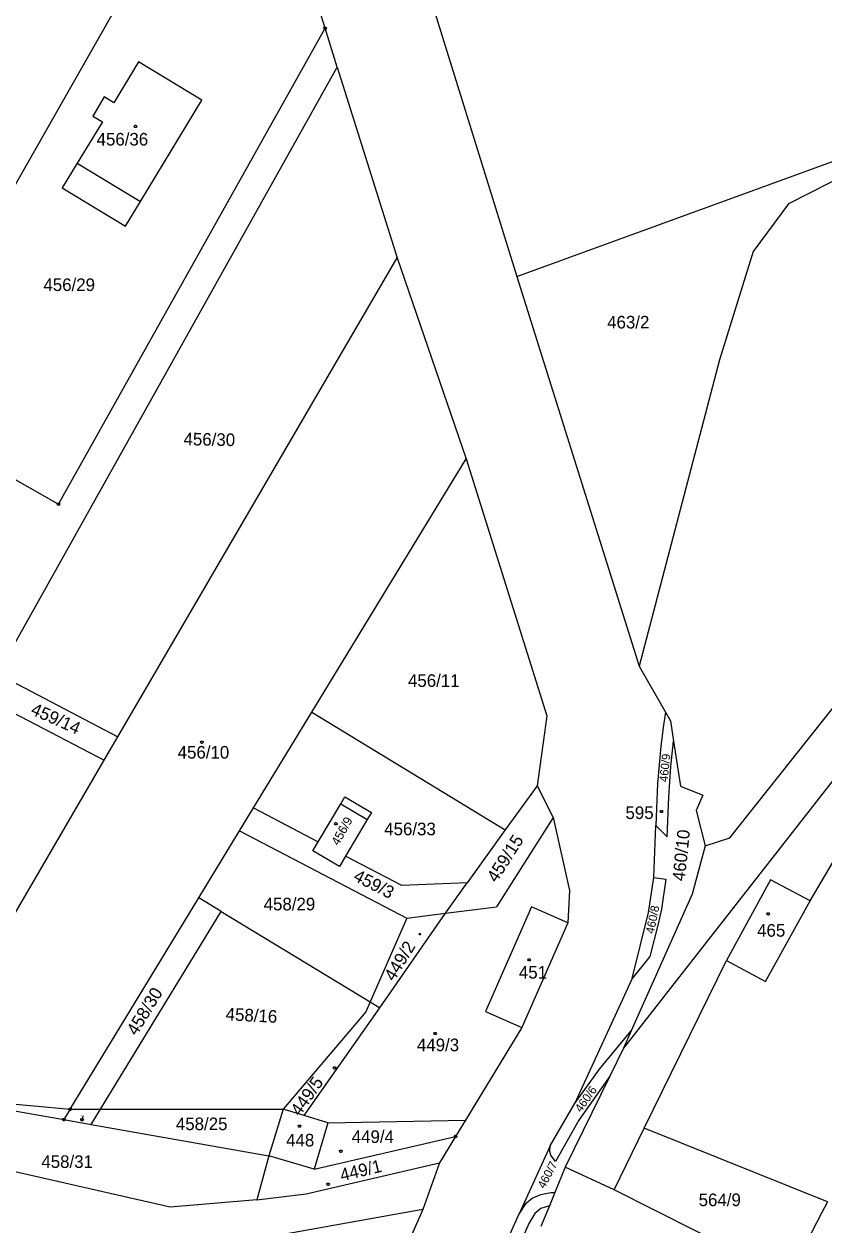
# Model space of a CAD drawing. Extents: x -634640 to -629202, y -1196156 to -1190068.
# Drawn here: x -631593.2 to -631485.4, y -1192430.1 to -1192268.2 of the extents above; entities that cross this region are included whole.
import ezdxf

# ---------------------------------------------------------------- set-up
doc = ezdxf.new("R2010")
doc.units = 0
for name, color, linetype in [('Vrstva 1', 7, 'Continuous'), ('Vrstva 2', 7, 'Continuous'), ('Vrstva 3', 7, 'Continuous'), ('Vrstva 4', 7, 'Continuous'), ('Vrstva 5', 7, 'Continuous'), ('Vrstva 7', 7, 'Continuous'), ('Vrstva 8', 7, 'Continuous')]:
    doc.layers.add(name, color=color, linetype=linetype)

msp = doc.modelspace()

# ---------------------------------------------------------------- linework, layer by layer
at = {"layer": 'Vrstva 1'}
for p, q in [((-631562.06, -1192188.79), (-631526.81, -1192302.22)), ((-631611.53, -1192319.92), (-631563.25, -1192234.99)), ((-631552.68, -1192268.74), (-631557.54, -1192253.21)), ((-631551.04, -1192273.99), (-631552.68, -1192268.74)), ((-631596.84, -1192355.81), (-631551.04, -1192273.99)), ((-631577.8, -1192273.3), (-631581.15, -1192278.82)), ((-631569.29, -1192278.43), (-631577.8, -1192273.3)), ((-631551.04, -1192273.99), (-631542.97, -1192299.72)), ((-631582.43, -1192278.02), (-631583.98, -1192280.59)), ((-631581.15, -1192278.82), (-631582.43, -1192278.02)), ((-631577.54, -1192292.12), (-631569.29, -1192278.43)), ((-631583.98, -1192280.59), (-631582.69, -1192281.35)), ((-631526.81, -1192302.22), (-631465.53, -1192279.88)), ((-631465.53, -1192279.88), (-631490.22, -1192292.44)), ((-631582.69, -1192281.35), (-631586.08, -1192286.94)), ((-631586.08, -1192286.94), (-631588.1, -1192290.27)), ((-631588.1, -1192290.27), (-631579.56, -1192295.46)), ((-631579.56, -1192295.46), (-631577.54, -1192292.12)), ((-631490.22, -1192292.44), (-631494.96, -1192298.85)), ((-631580.61, -1192364.32), (-631542.97, -1192299.72)), ((-631542.97, -1192299.72), (-631533.67, -1192326.82)), ((-631494.96, -1192298.85), (-631499.5, -1192313.48)), ((-631526.81, -1192302.22), (-631510.34, -1192354.77)), ((-631499.5, -1192313.48), (-631510.34, -1192354.77)), ((-631554.46, -1192360.99), (-631533.67, -1192326.82)), ((-631533.67, -1192326.82), (-631522.8, -1192361.49)), ((-631498.14, -1192377.93), (-631471.55, -1192344.46)), ((-631466.86, -1192347.91), (-631512.45, -1192406.32)), ((-631510.34, -1192354.77), (-631506.79, -1192360.97)), ((-631596.84, -1192355.81), (-631580.61, -1192364.32)), ((-631598.65, -1192359.03), (-631582.45, -1192367.48)), ((-631562.31, -1192373.9), (-631554.46, -1192360.99)), ((-631554.46, -1192360.99), (-631528.38, -1192376.86)), ((-631522.8, -1192361.49), (-631524.09, -1192370.93)), ((-631506.79, -1192360.97), (-631507.07, -1192362.72)), ((-631506.79, -1192360.97), (-631506.11, -1192362.16)), ((-631487.31, -1192386.45), (-631471.97, -1192360.34)), ((-631507.07, -1192362.72), (-631507.43, -1192365.56)), ((-631506.11, -1192362.16), (-631505.69, -1192364.89)), ((-631582.45, -1192367.48), (-631580.61, -1192364.32)), ((-631507.43, -1192365.56), (-631507.88, -1192370.62)), ((-631506.05, -1192368.32), (-631505.69, -1192364.89)), ((-631505.69, -1192364.89), (-631504.76, -1192370.98)), ((-631607.4, -1192410.3), (-631582.45, -1192367.48)), ((-631506.34, -1192372.46), (-631506.05, -1192368.32)), ((-631524.09, -1192370.93), (-631528.38, -1192376.86)), ((-631524.09, -1192370.93), (-631521.94, -1192375.21)), ((-631507.88, -1192370.62), (-631508.11, -1192376.26)), ((-631504.76, -1192370.98), (-631501.75, -1192372.19)), ((-631550.55, -1192373.34), (-631550, -1192372.4)), ((-631550, -1192372.4), (-631546.43, -1192374.51)), ((-631506.55, -1192377.78), (-631506.34, -1192372.46)), ((-631501.75, -1192372.19), (-631502.66, -1192374.25)), ((-631564.19, -1192377), (-631562.31, -1192373.9)), ((-631562.31, -1192373.9), (-631553.59, -1192378.47)), ((-631553.59, -1192378.47), (-631550.55, -1192373.34)), ((-631546.43, -1192374.51), (-631546.99, -1192375.46)), ((-631502.66, -1192374.25), (-631501.46, -1192379.03)), ((-631546.99, -1192375.46), (-631549.9, -1192380.4)), ((-631521.94, -1192375.21), (-631529.59, -1192387.26)), ((-631521.94, -1192375.21), (-631519.73, -1192385.06)), ((-631569.68, -1192386.03), (-631564.19, -1192377)), ((-631564.19, -1192377), (-631541.65, -1192388.76)), ((-631528.38, -1192376.86), (-631533.54, -1192383.99)), ((-631508.35, -1192383.3), (-631508.11, -1192376.26)), ((-631508.11, -1192376.26), (-631506.55, -1192377.78)), ((-631554.33, -1192379.71), (-631553.59, -1192378.47)), ((-631501.46, -1192379.03), (-631503.19, -1192385.52)), ((-631501.46, -1192379.03), (-631498.14, -1192377.93)), ((-631550.72, -1192381.79), (-631554.33, -1192379.71)), ((-631549.9, -1192380.4), (-631550.72, -1192381.79)), ((-631542.31, -1192384.38), (-631549.9, -1192380.4)), ((-631533.54, -1192383.99), (-631542.31, -1192384.38)), ((-631536.42, -1192388.11), (-631533.54, -1192383.99)), ((-631509.09, -1192387.99), (-631508.35, -1192383.3)), ((-631508.35, -1192383.3), (-631506.75, -1192383.52)), ((-631506.75, -1192383.52), (-631507.32, -1192387.57)), ((-631492.65, -1192383.6), (-631498.55, -1192394.46)), ((-631487.31, -1192386.45), (-631492.65, -1192383.6)), ((-631519.73, -1192385.06), (-631519.95, -1192389.39)), ((-631503.19, -1192385.52), (-631511.41, -1192403.98)), ((-631587.02, -1192414.54), (-631569.68, -1192386.03)), ((-631566.69, -1192387.85), (-631569.68, -1192386.03)), ((-631536.42, -1192388.11), (-631529.59, -1192387.26)), ((-631524.85, -1192387.24), (-631531.04, -1192401.35)), ((-631519.95, -1192389.39), (-631524.85, -1192387.24)), ((-631493.32, -1192397.32), (-631487.31, -1192386.45)), ((-631582.92, -1192414.54), (-631566.69, -1192387.85)), ((-631566.69, -1192387.85), (-631546.6, -1192400.07)), ((-631541.65, -1192388.76), (-631546.6, -1192400.07)), ((-631545.31, -1192400.85), (-631536.42, -1192388.11)), ((-631541.65, -1192388.76), (-631536.42, -1192388.11)), ((-631511.3, -1192396.91), (-631509.09, -1192387.99)), ((-631507.32, -1192387.57), (-631507.76, -1192389.52)), ((-631519.95, -1192389.39), (-631526.14, -1192403.5)), ((-631507.76, -1192389.52), (-631508.9, -1192393.94)), ((-631508.9, -1192393.94), (-631511.3, -1192396.91)), ((-631509.66, -1192417.1), (-631498.55, -1192394.46)), ((-631498.55, -1192394.46), (-631493.32, -1192397.32)), ((-631511.3, -1192396.91), (-631519.05, -1192413.81)), ((-631546.6, -1192400.07), (-631547.18, -1192401.4)), ((-631546.6, -1192400.07), (-631545.31, -1192400.85)), ((-631547.18, -1192401.4), (-631558.3, -1192414.52)), ((-631555.48, -1192415.4), (-631545.31, -1192400.85)), ((-631531.04, -1192401.35), (-631526.14, -1192403.5)), ((-631526.14, -1192403.5), (-631533.76, -1192416.02)), ((-631515.67, -1192409.13), (-631511.41, -1192403.98)), ((-631511.41, -1192403.98), (-631512.45, -1192406.32)), ((-631512.45, -1192406.32), (-631514.29, -1192410.06)), ((-631514.29, -1192410.06), (-631520.31, -1192422.34)), ((-631519.05, -1192413.81), (-631515.67, -1192409.13)), ((-631514.29, -1192410.06), (-631518.49, -1192416.03)), ((-631608.55, -1192412.27), (-631587.87, -1192415.94)), ((-631597.02, -1192413.6), (-631587.02, -1192414.54)), ((-631587.02, -1192414.54), (-631587.87, -1192415.94)), ((-631587.02, -1192414.54), (-631582.92, -1192414.54)), ((-631584.18, -1192416.59), (-631582.92, -1192414.54)), ((-631582.92, -1192414.54), (-631558.3, -1192414.52)), ((-631558.3, -1192414.52), (-631560.26, -1192420.83)), ((-631555.48, -1192415.4), (-631558.3, -1192414.52)), ((-631522.34, -1192419.46), (-631519.05, -1192413.81)), ((-631587.87, -1192415.94), (-631584.18, -1192416.59)), ((-631584.18, -1192416.59), (-631560.26, -1192420.83)), ((-631552.31, -1192416.38), (-631555.48, -1192415.4)), ((-631552.31, -1192416.38), (-631554.15, -1192422.64)), ((-631552.31, -1192416.38), (-631533.76, -1192416.02)), ((-631533.76, -1192416.02), (-631535.08, -1192418.2)), ((-631518.49, -1192416.03), (-631521.62, -1192421.57)), ((-631573.53, -1192427.73), (-631617.48, -1192417.8)), ((-631554.15, -1192422.64), (-631535.08, -1192418.2)), ((-631535.08, -1192418.2), (-631537.26, -1192421.78)), ((-631513.73, -1192425.4), (-631509.66, -1192417.1)), ((-631484.94, -1192427.03), (-631509.66, -1192417.1)), ((-631522.34, -1192419.46), (-631526.57, -1192428.73)), ((-631522.38, -1192420.22), (-631522.34, -1192419.46)), ((-631560.26, -1192420.83), (-631561.86, -1192426.76)), ((-631554.15, -1192422.64), (-631560.26, -1192420.83)), ((-631522.23, -1192420.75), (-631522.38, -1192420.22)), ((-631521.62, -1192421.57), (-631522.23, -1192420.75)), ((-631555.2, -1192425.95), (-631537.26, -1192421.78)), ((-631537.26, -1192421.78), (-631539.49, -1192428.06)), ((-631520.31, -1192422.34), (-631521.72, -1192425.78)), ((-631513.73, -1192425.4), (-631520.31, -1192422.34)), ((-631561.86, -1192426.76), (-631555.2, -1192425.95)), ((-631524.76, -1192426.54), (-631523.58, -1192426.02)), ((-631523.58, -1192426.02), (-631522.25, -1192425.75)), ((-631521.72, -1192425.78), (-631522.44, -1192427.56)), ((-631522.25, -1192425.75), (-631521.72, -1192425.78)), ((-631490.28, -1192437.19), (-631513.73, -1192425.4)), ((-631561.86, -1192426.76), (-631573.53, -1192427.73)), ((-631526.57, -1192428.73), (-631525.51, -1192427.18)), ((-631525.51, -1192427.18), (-631524.76, -1192426.54)), ((-631523.61, -1192427.91), (-631524.42, -1192428.62)), ((-631522.44, -1192427.56), (-631523.61, -1192427.91)), ((-631522.44, -1192427.56), (-631523.59, -1192430.36)), ((-631484.94, -1192427.03), (-631485.75, -1192428.57)), ((-631539.49, -1192428.06), (-631563.09, -1192432.29)), ((-631539.49, -1192428.06), (-631545.2, -1192440.97)), ((-631529.49, -1192435.33), (-631526.57, -1192428.73)), ((-631524.42, -1192428.62), (-631525.2, -1192429.94)), ((-631485.75, -1192428.57), (-631490.28, -1192437.19)), ((-631525.2, -1192429.94), (-631527.92, -1192436.1))]:
    msp.add_line(p, q, dxfattribs=at)
msp.add_lwpolyline([(-631611.53, -1192319.92), (-631588.62, -1192332.93), (-631552.68, -1192268.74)], dxfattribs=at)
at = {"layer": 'Vrstva 3'}
for points in [[(-631569.2, -1192364.9), (-631569.11, -1192365.05), (-631569.2, -1192365.2), (-631569.38, -1192365.2), (-631569.47, -1192365.05), (-631569.38, -1192364.9), (-631569.2, -1192364.9)], [(-631539.84, -1192390.82), (-631539.779, -1192390.92), (-631539.84, -1192391.02), (-631539.96, -1192391.02), (-631540.021, -1192390.92), (-631539.96, -1192390.82), (-631539.84, -1192390.82)], [(-631537.75, -1192404.17), (-631537.66, -1192404.32), (-631537.75, -1192404.47), (-631537.93, -1192404.47), (-631538.02, -1192404.32), (-631537.93, -1192404.17), (-631537.75, -1192404.17)], [(-631551.33, -1192408.82), (-631551.24, -1192408.97), (-631551.33, -1192409.12), (-631551.51, -1192409.12), (-631551.6, -1192408.97), (-631551.51, -1192408.82), (-631551.33, -1192408.82)], [(-631550.46, -1192420.06), (-631550.37, -1192420.21), (-631550.46, -1192420.36), (-631550.64, -1192420.36), (-631550.73, -1192420.21), (-631550.64, -1192420.06), (-631550.46, -1192420.06)], [(-631552.18, -1192424.51), (-631552.09, -1192424.66), (-631552.18, -1192424.81), (-631552.36, -1192424.81), (-631552.45, -1192424.66), (-631552.36, -1192424.51), (-631552.18, -1192424.51)]]:
    msp.add_lwpolyline(points, dxfattribs=at)
at = {"layer": 'Vrstva 4'}
for p, q in [((-631586.08, -1192286.94), (-631577.54, -1192292.12)), ((-631550.55, -1192373.34), (-631546.99, -1192375.46))]:
    msp.add_line(p, q, dxfattribs=at)
at = {"layer": 'Vrstva 5'}
for points in [[(-631578.14, -1192281.83), (-631578.05, -1192281.98), (-631578.14, -1192282.13), (-631578.32, -1192282.13), (-631578.41, -1192281.98), (-631578.32, -1192281.83), (-631578.14, -1192281.83)], [(-631551.12, -1192375.88), (-631551.03, -1192376.03), (-631551.12, -1192376.18), (-631551.3, -1192376.18), (-631551.39, -1192376.03), (-631551.3, -1192375.88), (-631551.12, -1192375.88)], [(-631492.86, -1192388.05), (-631492.77, -1192388.2), (-631492.86, -1192388.35), (-631493.04, -1192388.35), (-631493.13, -1192388.2), (-631493.04, -1192388.05), (-631492.86, -1192388.05)], [(-631525.06, -1192394.24), (-631524.97, -1192394.39), (-631525.06, -1192394.54), (-631525.24, -1192394.54), (-631525.33, -1192394.39), (-631525.24, -1192394.24), (-631525.06, -1192394.24)], [(-631556.01, -1192416.67), (-631555.92, -1192416.82), (-631556.01, -1192416.97), (-631556.19, -1192416.97), (-631556.28, -1192416.82), (-631556.19, -1192416.67), (-631556.01, -1192416.67)]]:
    msp.add_lwpolyline(points, dxfattribs=at)
at = {"layer": 'Vrstva 7'}
msp.add_line((-631585.34, -1192415.47), (-631585.42, -1192415.96), dxfattribs=at)
msp.add_lwpolyline([(-631585.531, -1192416.095), (-631585.598, -1192415.933), (-631585.486, -1192415.798), (-631585.309, -1192415.825), (-631585.242, -1192415.987), (-631585.354, -1192416.122), (-631585.531, -1192416.095)], dxfattribs=at)
at = {"layer": 'Vrstva 8'}
for points in [[(-631552.59, -1192268.59), (-631552.5, -1192268.74), (-631552.59, -1192268.89), (-631552.77, -1192268.89), (-631552.86, -1192268.74), (-631552.77, -1192268.59), (-631552.59, -1192268.59)], [(-631588.53, -1192332.78), (-631588.44, -1192332.93), (-631588.53, -1192333.08), (-631588.71, -1192333.08), (-631588.8, -1192332.93), (-631588.71, -1192332.78), (-631588.53, -1192332.78)], [(-631507.23, -1192374.24), (-631507.14, -1192374.39), (-631507.23, -1192374.54), (-631507.41, -1192374.54), (-631507.5, -1192374.39), (-631507.41, -1192374.24), (-631507.23, -1192374.24)], [(-631586.93, -1192414.39), (-631586.84, -1192414.54), (-631586.93, -1192414.69), (-631587.11, -1192414.69), (-631587.2, -1192414.54), (-631587.11, -1192414.39), (-631586.93, -1192414.39)], [(-631587.78, -1192415.79), (-631587.69, -1192415.94), (-631587.78, -1192416.09), (-631587.96, -1192416.09), (-631588.05, -1192415.94), (-631587.96, -1192415.79), (-631587.78, -1192415.79)], [(-631534.99, -1192418.05), (-631534.9, -1192418.2), (-631534.99, -1192418.35), (-631535.17, -1192418.35), (-631535.26, -1192418.2), (-631535.17, -1192418.05), (-631534.99, -1192418.05)]]:
    msp.add_lwpolyline(points, dxfattribs=at)

# ---------------------------------------------------------------- texts
at = {"layer": 'Vrstva 2'}
for s, height, p in [('456/36', 1.7, (-631583.468, -1192284.57)), ('456/29', 1.7, (-631590.633, -1192304.19)), ('463/2', 1.7, (-631514.653, -1192309.24)), ('456/11', 1.7, (-631541.493, -1192357.58)), ('456/10', 1.7, (-631572.543, -1192367.25)), ('456/33', 1.7, (-631544.698, -1192377.59)), ('458/29', 1.7, (-631560.949, -1192387.72)), ('465', 1.7, (-631494.443, -1192391.27)), ('451', 1.7, (-631526.553, -1192396.92)), ('449/3', 1.7, (-631540.293, -1192406.71)), ('458/31', 0.1, (-631585.601, -1192415.47)), ('458/25', 1.7, (-631572.779, -1192417.36)), ('448', 1.7, (-631557.923, -1192419.56)), ('449/4', 1.7, (-631549.079, -1192419.09)), ('564/9', 1.7, (-631502.323, -1192427.61))]:
    msp.add_text(s, height=height, dxfattribs=at).set_placement(p)
for s, height, rotation, p in [('456/30', 1.7, 358.95806, (-631571.763, -1192324.984)), ('459/14', 1.7, 335.86786, (-631592.473, -1192361.207)), ('460/9', 1.14, 84.05291, (-631506.514, -1192370.452)), ('456/9', 1.2, 60.90541, (-631550.859, -1192379.064)), ('459/15', 1.7, 57.58226, (-631529.563, -1192384.09)), ('460/10', 1.7, 84.05291, (-631504.195, -1192383.834)), ('459/3', 1.7, 332.71659, (-631548.999, -1192383.609)), ('460/8', 1.14, 78.55251, (-631508.358, -1192390.934)), ('449/2', 1.7, 58.3844, (-631543.396, -1192397.398)), ('458/30', 1.7, 58.67088, (-631578.092, -1192404.733)), ('458/16', 1.7, 357.01, (-631566.103, -1192402.532)), ('449/5', 1.7, 54.94665, (-631556.078, -1192415.572)), ('460/6', 1.14, 54.60288, (-631518.178, -1192415.04)), ('449/1', 1.7, 13.5218, (-631550.431, -1192424.277)), ('460/7', 1.14, 62.28051, (-631523.096, -1192425.339))]:
    msp.add_text(s, height=height, rotation=rotation, dxfattribs=at).set_placement(p)
at = {"layer": 'Vrstva 7'}
msp.add_text('458/31', height=1.7, dxfattribs=at).set_placement((-631590.911, -1192422.46))
at = {"layer": 'Vrstva 8'}
msp.add_text('595', height=1.7, dxfattribs=at).set_placement((-631512.183, -1192375.4))

doc.saveas('drawing.dxf')
